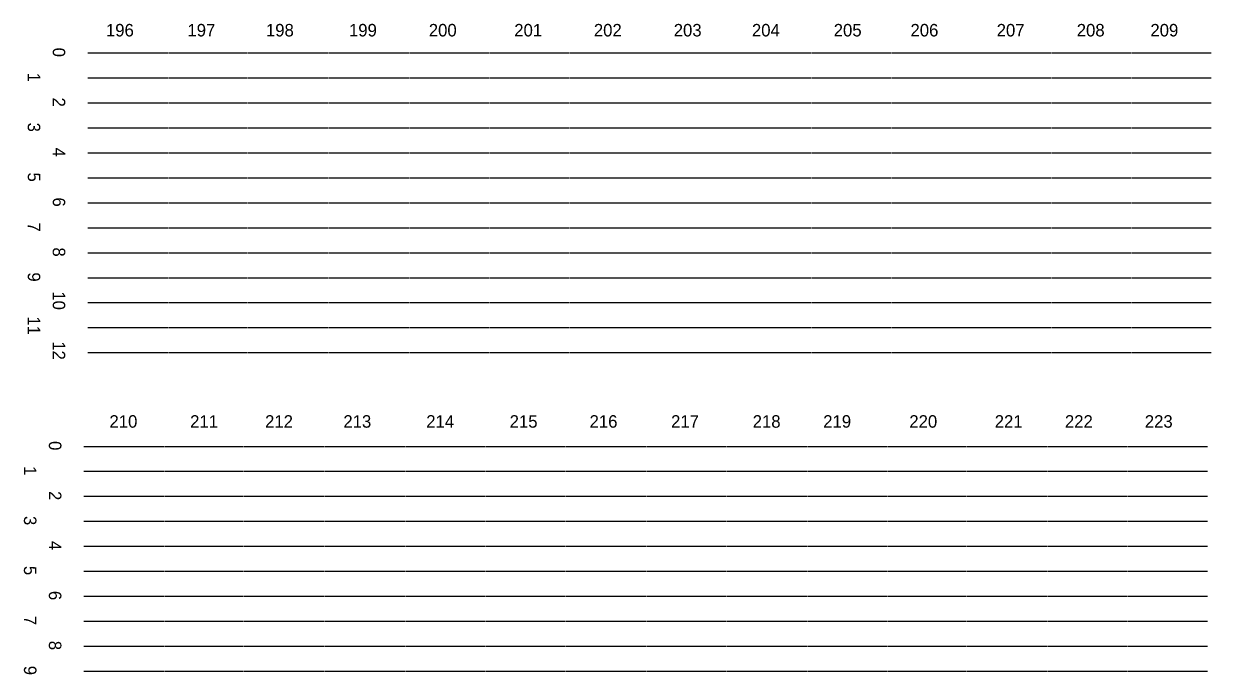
# Model space of a CAD drawing. Extents: x 11193 to 12507, y 10092 to 10555.
# Drawn here: x 11683 to 11889, y 10441.2 to 10554.1 of the extents above; entities that cross this region are included whole.
import ezdxf

# ---------------------------------------------------------------- set-up
doc = ezdxf.new("R2010")
doc.units = 0
doc.layers.add('Level 2', color=7, linetype='Continuous')

msp = doc.modelspace()

# ---------------------------------------------------------------- linework, layer by layer
at = {"layer": 'Level 2'}
for p, q in [((11694.09, 10549.04), (11708.02, 10549.04)), ((11708.14, 10549.04), (11721.7, 10549.04)), ((11721.81, 10549.04), (11735.78, 10549.04)), ((11735.9, 10549.04), (11749.86, 10549.04)), ((11749.98, 10549.04), (11763.75, 10549.04)), ((11763.86, 10549.04), (11777.63, 10549.04)), ((11777.73, 10549.04), (11791.71, 10549.04)), ((11791.81, 10549.04), (11805.59, 10549.04)), ((11805.69, 10549.04), (11819.68, 10549.04)), ((11819.78, 10549.04), (11833.55, 10549.04)), ((11833.65, 10549.04), (11847.23, 10549.04)), ((11847.33, 10549.04), (11861.31, 10549.04)), ((11861.41, 10549.04), (11875.19, 10549.04)), ((11875.3, 10549.04), (11889.03, 10549.04)), ((11694.09, 10544.71), (11708.02, 10544.71)), ((11708.14, 10544.71), (11721.7, 10544.71)), ((11721.81, 10544.71), (11735.78, 10544.71)), ((11735.9, 10544.71), (11749.86, 10544.71)), ((11749.98, 10544.71), (11763.75, 10544.71)), ((11763.86, 10544.71), (11777.63, 10544.71)), ((11777.73, 10544.71), (11791.71, 10544.71)), ((11791.81, 10544.71), (11805.59, 10544.71)), ((11805.69, 10544.71), (11819.68, 10544.71)), ((11819.78, 10544.71), (11833.55, 10544.71)), ((11833.65, 10544.71), (11847.23, 10544.71)), ((11847.33, 10544.71), (11861.31, 10544.71)), ((11861.41, 10544.71), (11875.19, 10544.71)), ((11875.3, 10544.71), (11889.03, 10544.71)), ((11694.09, 10540.38), (11708.02, 10540.38)), ((11708.14, 10540.38), (11721.7, 10540.38)), ((11721.81, 10540.38), (11735.78, 10540.38)), ((11735.9, 10540.38), (11749.86, 10540.38)), ((11749.98, 10540.38), (11763.75, 10540.38)), ((11763.86, 10540.38), (11777.63, 10540.38)), ((11777.73, 10540.38), (11791.71, 10540.38)), ((11791.81, 10540.38), (11805.59, 10540.38)), ((11805.69, 10540.38), (11819.68, 10540.38)), ((11819.78, 10540.38), (11833.55, 10540.38)), ((11833.65, 10540.38), (11847.23, 10540.38)), ((11847.33, 10540.38), (11861.31, 10540.38)), ((11861.41, 10540.38), (11875.19, 10540.38)), ((11875.3, 10540.38), (11889.03, 10540.38)), ((11694.09, 10536.04), (11708.02, 10536.04)), ((11708.14, 10536.04), (11721.7, 10536.04)), ((11721.81, 10536.04), (11735.78, 10536.04)), ((11735.9, 10536.04), (11749.86, 10536.04)), ((11749.98, 10536.04), (11763.75, 10536.04)), ((11763.86, 10536.04), (11777.63, 10536.04)), ((11777.73, 10536.04), (11791.71, 10536.04)), ((11791.81, 10536.04), (11805.59, 10536.04)), ((11805.69, 10536.04), (11819.68, 10536.04)), ((11819.78, 10536.04), (11833.55, 10536.04)), ((11833.65, 10536.04), (11847.23, 10536.04)), ((11847.33, 10536.04), (11861.31, 10536.04)), ((11861.41, 10536.04), (11875.19, 10536.04)), ((11875.3, 10536.04), (11889.03, 10536.04)), ((11694.09, 10531.71), (11708.02, 10531.71)), ((11708.14, 10531.71), (11721.7, 10531.71)), ((11721.81, 10531.71), (11735.78, 10531.71)), ((11735.9, 10531.71), (11749.86, 10531.71)), ((11749.98, 10531.71), (11763.75, 10531.71)), ((11763.86, 10531.71), (11777.63, 10531.71)), ((11777.73, 10531.71), (11791.71, 10531.71)), ((11791.81, 10531.71), (11805.59, 10531.71)), ((11805.69, 10531.71), (11819.68, 10531.71)), ((11819.78, 10531.71), (11833.55, 10531.71)), ((11833.65, 10531.71), (11847.23, 10531.71)), ((11847.33, 10531.71), (11861.31, 10531.71)), ((11861.41, 10531.71), (11875.19, 10531.71)), ((11875.3, 10531.71), (11889.03, 10531.71)), ((11694.09, 10527.38), (11708.02, 10527.38)), ((11708.14, 10527.38), (11721.7, 10527.38)), ((11721.81, 10527.38), (11735.78, 10527.38)), ((11735.9, 10527.38), (11749.86, 10527.38)), ((11749.98, 10527.38), (11763.75, 10527.38)), ((11763.86, 10527.38), (11777.63, 10527.38)), ((11777.73, 10527.38), (11791.71, 10527.38)), ((11791.81, 10527.38), (11805.59, 10527.38)), ((11805.69, 10527.38), (11819.68, 10527.38)), ((11819.78, 10527.38), (11833.55, 10527.38)), ((11833.65, 10527.38), (11847.23, 10527.38)), ((11847.33, 10527.38), (11861.31, 10527.38)), ((11861.41, 10527.38), (11875.19, 10527.38)), ((11875.3, 10527.38), (11889.03, 10527.38)), ((11694.09, 10523.05), (11708.02, 10523.05)), ((11708.14, 10523.05), (11721.7, 10523.05)), ((11721.81, 10523.05), (11735.78, 10523.05)), ((11735.9, 10523.05), (11749.86, 10523.05)), ((11749.98, 10523.05), (11763.75, 10523.05)), ((11763.86, 10523.05), (11777.63, 10523.05)), ((11777.73, 10523.05), (11791.71, 10523.05)), ((11791.81, 10523.05), (11805.59, 10523.05)), ((11805.69, 10523.05), (11819.68, 10523.05)), ((11819.78, 10523.05), (11833.55, 10523.05)), ((11833.65, 10523.05), (11847.23, 10523.05)), ((11847.33, 10523.05), (11861.31, 10523.05)), ((11861.41, 10523.05), (11875.19, 10523.05)), ((11875.3, 10523.05), (11889.03, 10523.05)), ((11694.09, 10518.72), (11708.02, 10518.72)), ((11708.14, 10518.72), (11721.7, 10518.72)), ((11721.81, 10518.72), (11735.78, 10518.72)), ((11735.9, 10518.72), (11749.86, 10518.72)), ((11749.98, 10518.72), (11763.75, 10518.72)), ((11763.86, 10518.72), (11777.63, 10518.72)), ((11777.73, 10518.72), (11791.71, 10518.72)), ((11791.81, 10518.72), (11805.59, 10518.72)), ((11805.69, 10518.72), (11819.68, 10518.72)), ((11819.78, 10518.72), (11833.55, 10518.72)), ((11833.65, 10518.72), (11847.23, 10518.72)), ((11847.33, 10518.72), (11861.31, 10518.72)), ((11861.41, 10518.72), (11875.19, 10518.72)), ((11875.3, 10518.72), (11889.03, 10518.72)), ((11694.09, 10514.38), (11708.02, 10514.38)), ((11708.14, 10514.38), (11721.7, 10514.38)), ((11721.81, 10514.38), (11735.78, 10514.38)), ((11735.9, 10514.38), (11749.86, 10514.38)), ((11749.98, 10514.38), (11763.75, 10514.38)), ((11763.86, 10514.38), (11777.63, 10514.38)), ((11777.73, 10514.38), (11791.71, 10514.38)), ((11791.81, 10514.38), (11805.59, 10514.38)), ((11805.69, 10514.38), (11819.68, 10514.38)), ((11819.78, 10514.38), (11833.55, 10514.38)), ((11833.65, 10514.38), (11847.23, 10514.38)), ((11847.33, 10514.38), (11861.31, 10514.38)), ((11861.41, 10514.38), (11875.19, 10514.38)), ((11875.3, 10514.38), (11889.03, 10514.38)), ((11694.09, 10510.05), (11708.02, 10510.05)), ((11708.14, 10510.05), (11721.7, 10510.05)), ((11721.81, 10510.05), (11735.78, 10510.05)), ((11735.9, 10510.05), (11749.86, 10510.05)), ((11749.98, 10510.05), (11763.75, 10510.05)), ((11763.86, 10510.05), (11777.63, 10510.05)), ((11777.73, 10510.05), (11791.71, 10510.05)), ((11791.81, 10510.05), (11805.59, 10510.05)), ((11805.69, 10510.05), (11819.68, 10510.05)), ((11819.78, 10510.05), (11833.55, 10510.05)), ((11833.65, 10510.05), (11847.23, 10510.05)), ((11847.33, 10510.05), (11861.31, 10510.05)), ((11861.41, 10510.05), (11875.19, 10510.05)), ((11875.3, 10510.05), (11889.03, 10510.05)), ((11694.09, 10505.72), (11708.02, 10505.72)), ((11708.14, 10505.72), (11721.7, 10505.72)), ((11721.81, 10505.72), (11735.78, 10505.72)), ((11735.9, 10505.72), (11749.86, 10505.72)), ((11749.98, 10505.72), (11763.75, 10505.72)), ((11763.86, 10505.72), (11777.63, 10505.72)), ((11777.73, 10505.72), (11791.71, 10505.72)), ((11791.81, 10505.72), (11805.59, 10505.72)), ((11805.69, 10505.72), (11819.68, 10505.72)), ((11819.78, 10505.72), (11833.55, 10505.72)), ((11833.65, 10505.72), (11847.23, 10505.72)), ((11847.33, 10505.72), (11861.31, 10505.72)), ((11861.41, 10505.72), (11875.19, 10505.72)), ((11875.3, 10505.72), (11889.03, 10505.72)), ((11694.09, 10501.39), (11708.02, 10501.39)), ((11708.14, 10501.39), (11721.7, 10501.39)), ((11721.81, 10501.39), (11735.78, 10501.39)), ((11735.9, 10501.39), (11749.86, 10501.39)), ((11749.98, 10501.39), (11763.75, 10501.39)), ((11763.86, 10501.39), (11777.63, 10501.39)), ((11777.73, 10501.39), (11791.71, 10501.39)), ((11791.81, 10501.39), (11805.59, 10501.39)), ((11805.69, 10501.39), (11819.68, 10501.39)), ((11819.78, 10501.39), (11833.55, 10501.39)), ((11833.65, 10501.39), (11847.23, 10501.39)), ((11847.33, 10501.39), (11861.31, 10501.39)), ((11861.41, 10501.39), (11875.19, 10501.39)), ((11875.3, 10501.39), (11889.03, 10501.39)), ((11694.09, 10497.06), (11708.02, 10497.06)), ((11708.14, 10497.06), (11721.7, 10497.06)), ((11721.81, 10497.06), (11735.78, 10497.06)), ((11735.9, 10497.06), (11749.86, 10497.06)), ((11749.98, 10497.06), (11763.75, 10497.06)), ((11763.86, 10497.06), (11777.63, 10497.06)), ((11777.73, 10497.06), (11791.71, 10497.06)), ((11791.81, 10497.06), (11805.59, 10497.06)), ((11805.69, 10497.06), (11819.68, 10497.06)), ((11819.78, 10497.06), (11833.55, 10497.06)), ((11833.65, 10497.06), (11847.23, 10497.06)), ((11847.33, 10497.06), (11861.31, 10497.06)), ((11861.41, 10497.06), (11875.19, 10497.06)), ((11875.3, 10497.06), (11889.03, 10497.06)), ((11693.42, 10480.78), (11707.34, 10480.78)), ((11707.44, 10480.78), (11721.02, 10480.78)), ((11721.12, 10480.78), (11735.1, 10480.78)), ((11735.2, 10480.78), (11749.18, 10480.78)), ((11749.29, 10480.78), (11763.06, 10480.78)), ((11763.17, 10480.78), (11776.94, 10480.78)), ((11777.05, 10480.78), (11791.02, 10480.78)), ((11791.13, 10480.78), (11804.91, 10480.78)), ((11805.02, 10480.78), (11818.99, 10480.78)), ((11819.09, 10480.78), (11832.87, 10480.78)), ((11832.98, 10480.78), (11846.54, 10480.78)), ((11846.65, 10480.78), (11860.62, 10480.78)), ((11860.73, 10480.78), (11874.51, 10480.78)), ((11874.62, 10480.78), (11888.36, 10480.78)), ((11693.42, 10476.45), (11707.34, 10476.45)), ((11707.44, 10476.45), (11721.02, 10476.45)), ((11721.12, 10476.45), (11735.1, 10476.45)), ((11735.2, 10476.45), (11749.18, 10476.45)), ((11749.29, 10476.45), (11763.06, 10476.45)), ((11763.17, 10476.45), (11776.94, 10476.45)), ((11777.05, 10476.45), (11791.02, 10476.45)), ((11791.13, 10476.45), (11804.91, 10476.45)), ((11805.02, 10476.45), (11818.99, 10476.45)), ((11819.09, 10476.45), (11832.87, 10476.45)), ((11832.98, 10476.45), (11846.54, 10476.45)), ((11846.65, 10476.45), (11860.62, 10476.45)), ((11860.73, 10476.45), (11874.51, 10476.45)), ((11874.62, 10476.45), (11888.36, 10476.45)), ((11693.42, 10472.12), (11707.34, 10472.12)), ((11707.44, 10472.12), (11721.02, 10472.12)), ((11721.12, 10472.12), (11735.1, 10472.12)), ((11735.2, 10472.12), (11749.18, 10472.12)), ((11749.29, 10472.12), (11763.06, 10472.12)), ((11763.17, 10472.12), (11776.94, 10472.12)), ((11777.05, 10472.12), (11791.02, 10472.12)), ((11791.13, 10472.12), (11804.91, 10472.12)), ((11805.02, 10472.12), (11818.99, 10472.12)), ((11819.09, 10472.12), (11832.87, 10472.12)), ((11832.98, 10472.12), (11846.54, 10472.12)), ((11846.65, 10472.12), (11860.62, 10472.12)), ((11860.73, 10472.12), (11874.51, 10472.12)), ((11874.62, 10472.12), (11888.36, 10472.12)), ((11693.42, 10467.79), (11707.34, 10467.79)), ((11707.44, 10467.79), (11721.02, 10467.79)), ((11721.12, 10467.79), (11735.1, 10467.79)), ((11735.2, 10467.79), (11749.18, 10467.79)), ((11749.29, 10467.79), (11763.06, 10467.79)), ((11763.17, 10467.79), (11776.94, 10467.79)), ((11777.05, 10467.79), (11791.02, 10467.79)), ((11791.13, 10467.79), (11804.91, 10467.79)), ((11805.02, 10467.79), (11818.99, 10467.79)), ((11819.09, 10467.79), (11832.87, 10467.79)), ((11832.98, 10467.79), (11846.54, 10467.79)), ((11846.65, 10467.79), (11860.62, 10467.79)), ((11860.73, 10467.79), (11874.51, 10467.79)), ((11874.62, 10467.79), (11888.36, 10467.79)), ((11693.42, 10463.46), (11707.34, 10463.46)), ((11707.44, 10463.46), (11721.02, 10463.46)), ((11721.12, 10463.46), (11735.1, 10463.46)), ((11735.2, 10463.46), (11749.18, 10463.46)), ((11749.29, 10463.46), (11763.06, 10463.46)), ((11763.17, 10463.46), (11776.94, 10463.46)), ((11777.05, 10463.46), (11791.02, 10463.46)), ((11791.13, 10463.46), (11804.91, 10463.46)), ((11805.02, 10463.46), (11818.99, 10463.46)), ((11819.09, 10463.46), (11832.87, 10463.46)), ((11832.98, 10463.46), (11846.54, 10463.46)), ((11846.65, 10463.46), (11860.62, 10463.46)), ((11860.73, 10463.46), (11874.51, 10463.46)), ((11874.62, 10463.46), (11888.36, 10463.46)), ((11693.42, 10459.12), (11707.34, 10459.12)), ((11707.44, 10459.12), (11721.02, 10459.12)), ((11721.12, 10459.12), (11735.1, 10459.12)), ((11735.2, 10459.12), (11749.18, 10459.12)), ((11749.29, 10459.12), (11763.06, 10459.12)), ((11763.17, 10459.12), (11776.94, 10459.12)), ((11777.05, 10459.12), (11791.02, 10459.12)), ((11791.13, 10459.12), (11804.91, 10459.12)), ((11805.02, 10459.12), (11818.99, 10459.12)), ((11819.09, 10459.12), (11832.87, 10459.12)), ((11832.98, 10459.12), (11846.54, 10459.12)), ((11846.65, 10459.12), (11860.62, 10459.12)), ((11860.73, 10459.12), (11874.51, 10459.12)), ((11874.62, 10459.12), (11888.36, 10459.12)), ((11693.42, 10454.79), (11707.34, 10454.79)), ((11707.44, 10454.79), (11721.02, 10454.79)), ((11721.12, 10454.79), (11735.1, 10454.79)), ((11735.2, 10454.79), (11749.18, 10454.79)), ((11749.29, 10454.79), (11763.06, 10454.79)), ((11763.17, 10454.79), (11776.94, 10454.79)), ((11777.05, 10454.79), (11791.02, 10454.79)), ((11791.13, 10454.79), (11804.91, 10454.79)), ((11805.02, 10454.79), (11818.99, 10454.79)), ((11819.09, 10454.79), (11832.87, 10454.79)), ((11832.98, 10454.79), (11846.54, 10454.79)), ((11846.65, 10454.79), (11860.62, 10454.79)), ((11860.73, 10454.79), (11874.51, 10454.79)), ((11874.62, 10454.79), (11888.36, 10454.79)), ((11693.42, 10450.46), (11707.34, 10450.46)), ((11707.44, 10450.46), (11721.02, 10450.46)), ((11721.12, 10450.46), (11735.1, 10450.46)), ((11735.2, 10450.46), (11749.18, 10450.46)), ((11749.29, 10450.46), (11763.06, 10450.46)), ((11763.17, 10450.46), (11776.94, 10450.46)), ((11777.05, 10450.46), (11791.02, 10450.46)), ((11791.13, 10450.46), (11804.91, 10450.46)), ((11805.02, 10450.46), (11818.99, 10450.46)), ((11819.09, 10450.46), (11832.87, 10450.46)), ((11832.98, 10450.46), (11846.54, 10450.46)), ((11846.65, 10450.46), (11860.62, 10450.46)), ((11860.73, 10450.46), (11874.51, 10450.46)), ((11874.62, 10450.46), (11888.36, 10450.46)), ((11693.42, 10446.13), (11707.34, 10446.13)), ((11707.44, 10446.13), (11721.02, 10446.13)), ((11721.12, 10446.13), (11735.1, 10446.13)), ((11735.2, 10446.13), (11749.18, 10446.13)), ((11749.29, 10446.13), (11763.06, 10446.13)), ((11763.17, 10446.13), (11776.94, 10446.13)), ((11777.05, 10446.13), (11791.02, 10446.13)), ((11791.13, 10446.13), (11804.91, 10446.13)), ((11805.02, 10446.13), (11818.99, 10446.13)), ((11819.09, 10446.13), (11832.87, 10446.13)), ((11832.98, 10446.13), (11846.54, 10446.13)), ((11846.65, 10446.13), (11860.62, 10446.13)), ((11860.73, 10446.13), (11874.51, 10446.13)), ((11874.62, 10446.13), (11888.36, 10446.13)), ((11693.42, 10441.8), (11707.34, 10441.8)), ((11707.44, 10441.8), (11721.02, 10441.8)), ((11721.12, 10441.8), (11735.1, 10441.8)), ((11735.2, 10441.8), (11749.18, 10441.8)), ((11749.29, 10441.8), (11763.06, 10441.8)), ((11763.17, 10441.8), (11776.94, 10441.8)), ((11777.05, 10441.8), (11791.02, 10441.8)), ((11791.13, 10441.8), (11804.91, 10441.8)), ((11805.02, 10441.8), (11818.99, 10441.8)), ((11819.09, 10441.8), (11832.87, 10441.8)), ((11832.98, 10441.8), (11846.54, 10441.8)), ((11846.65, 10441.8), (11860.62, 10441.8)), ((11860.73, 10441.8), (11874.51, 10441.8)), ((11874.62, 10441.8), (11888.36, 10441.8))]:
    msp.add_line(p, q, dxfattribs=at)

# ---------------------------------------------------------------- texts
for s, p in [('196', (11697.24, 10551.91)), ('197', (11711.38, 10551.91)), ('198', (11725, 10551.91)), ('199', (11739.41, 10551.91)), ('200', (11753.26, 10551.91)), ('201', (11768.09, 10551.91)), ('202', (11781.9, 10551.91)), ('203', (11795.76, 10551.91)), ('204', (11809.33, 10551.91)), ('205', (11823.52, 10551.91)), ('206', (11836.84, 10551.91)), ('207', (11851.8, 10551.91)), ('208', (11865.69, 10551.91)), ('209', (11878.47, 10551.91)), ('210', (11697.85, 10484.02)), ('211', (11711.85, 10484.02)), ('212', (11724.85, 10484.02)), ('213', (11738.44, 10484.02)), ('214', (11752.82, 10484.02)), ('215', (11767.29, 10484.02)), ('216', (11781.16, 10484.02)), ('217', (11795.3, 10484.02)), ('218', (11809.46, 10484.02)), ('219', (11821.7, 10484.02)), ('220', (11836.64, 10484.02)), ('221', (11851.46, 10484.02)), ('222', (11863.64, 10484.02)), ('223', (11877.5, 10484.02))]:
    msp.add_text(s, height=2.17, dxfattribs=at).set_placement(p)
for s, height, p in [('0', 2.17, (11688.01, 10549.96)), ('1', 2.17, (11683.68, 10545.63)), ('2', 2.17, (11688.01, 10541.3)), ('3', 2.17, (11683.68, 10536.96)), ('4', 2.17, (11688.01, 10532.63)), ('5', 2.17, (11683.68, 10528.3)), ('6', 2.17, (11688.01, 10523.97)), ('7', 2.17, (11683.68, 10519.64)), ('8', 2.17, (11688.01, 10515.3)), ('9', 2.17, (11683.68, 10510.97)), ('10', 2.166, (11688.01, 10507.68)), ('11', 2.166, (11683.68, 10503.34)), ('12', 2.166, (11688.01, 10499.01)), ('0', 2.17, (11687.34, 10481.7)), ('1', 2.17, (11683.01, 10477.36)), ('2', 2.17, (11687.34, 10473.03)), ('3', 2.17, (11683.01, 10468.7)), ('4', 2.17, (11687.34, 10464.37)), ('5', 2.17, (11683.01, 10460.04)), ('6', 2.17, (11687.34, 10455.7)), ('7', 2.17, (11683.01, 10451.37)), ('8', 2.17, (11687.34, 10447.04)), ('9', 2.17, (11683.01, 10442.71))]:
    msp.add_text(s, height=height, rotation=270, dxfattribs=at).set_placement(p)

doc.saveas('drawing.dxf')
